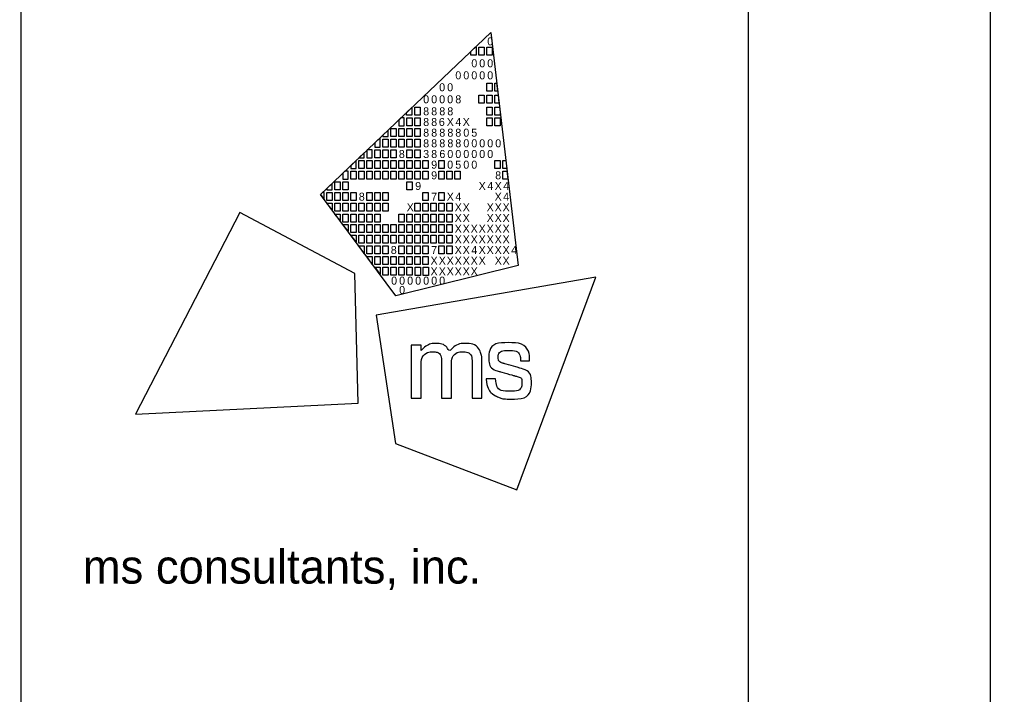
# Model space of a CAD drawing. Extents: x 0 to 34, y 0 to 22.
# Drawn here: x 31.997 to 34, y 2.72 to 4.113 of the extents above; entities that cross this region are included whole.
import ezdxf

# ---------------------------------------------------------------- set-up
doc = ezdxf.new("R2010")
doc.units = 0
for name, color, linetype in [('SH_Border', 7, 'Continuous'), ('SH_Cut_Line', 7, 'Continuous'), ('SH_Data', 7, 'Continuous')]:
    doc.layers.add(name, color=color, linetype=linetype)

msp = doc.modelspace()

# ---------------------------------------------------------------- linework, layer by layer
at = {"layer": 'SH_Border'}
for p, q in [((32, 0.5), (32, 21.5)), ((32.6175, 3.7519), (32.9688, 4.0861)), ((32.9688, 4.0861), (32.9688, 4.0861)), ((32.9688, 4.0861), (33.0253, 3.6052)), ((32.773, 3.543), (32.6175, 3.7519)), ((33.0253, 3.6052), (32.773, 3.543))]:
    msp.add_line(p, q, dxfattribs=at)
for points in [[(1.5, 21.5), (33.5, 21.5), (33.5, 0.5), (1.5, 0.5)], [(32.9279, 4.0472), (32.9369, 4.0558), (32.9389, 4.0558), (32.9389, 4.0393), (32.9279, 4.0393)], [(32.9444, 4.0558), (32.9554, 4.0558), (32.9554, 4.0393), (32.9444, 4.0393)], [(32.9609, 4.0558), (32.9719, 4.0558), (32.9719, 4.0393), (32.9609, 4.0393)], [(32.9606, 3.9815), (32.9716, 3.9815), (32.9716, 3.965), (32.9606, 3.965)], [(32.9771, 3.9815), (32.9811, 3.9815), (32.983, 3.965), (32.9771, 3.965)], [(32.9441, 3.9567), (32.9551, 3.9567), (32.9551, 3.9402), (32.9441, 3.9402)], [(32.9606, 3.9567), (32.9716, 3.9567), (32.9716, 3.9402), (32.9606, 3.9402)], [(32.9771, 3.9567), (32.984, 3.9567), (32.9859, 3.9402), (32.9771, 3.9402)], [(32.7953, 3.9211), (32.8064, 3.9316), (32.8064, 3.9154), (32.7953, 3.9154)], [(32.8123, 3.9319), (32.8233, 3.9319), (32.8233, 3.9154), (32.8123, 3.9154)], [(32.9606, 3.9319), (32.9716, 3.9319), (32.9716, 3.9154), (32.9606, 3.9154)], [(32.9771, 3.9319), (32.9869, 3.9319), (32.9881, 3.9218), (32.9881, 3.9154), (32.9771, 3.9154)], [(32.7958, 3.9099), (32.8068, 3.9099), (32.8068, 3.8934), (32.7958, 3.8934)], [(32.8123, 3.9099), (32.8233, 3.9099), (32.8233, 3.8934), (32.8123, 3.8934)], [(32.9606, 3.9099), (32.9716, 3.9099), (32.9716, 3.8934), (32.9606, 3.8934)], [(32.9771, 3.9099), (32.9881, 3.9099), (32.9881, 3.8934), (32.9771, 3.8934)], [(32.7627, 3.8879), (32.7737, 3.8879), (32.7737, 3.8714), (32.7627, 3.8714)], [(32.7793, 3.8879), (32.7903, 3.8879), (32.7903, 3.8714), (32.7793, 3.8714)], [(32.7958, 3.8879), (32.8068, 3.8879), (32.8068, 3.8714), (32.7958, 3.8714)], [(32.8123, 3.8879), (32.8233, 3.8879), (32.8233, 3.8714), (32.8123, 3.8714)], [(32.7462, 3.8659), (32.7572, 3.8659), (32.7572, 3.8494), (32.7462, 3.8494)], [(32.7627, 3.8659), (32.7737, 3.8659), (32.7737, 3.8494), (32.7627, 3.8494)], [(32.7793, 3.8659), (32.7903, 3.8659), (32.7903, 3.8494), (32.7793, 3.8494)], [(32.7958, 3.8659), (32.8068, 3.8659), (32.8068, 3.8494), (32.7958, 3.8494)], [(32.8123, 3.8659), (32.8233, 3.8659), (32.8233, 3.8494), (32.8123, 3.8494)], [(32.7297, 3.8439), (32.7407, 3.8439), (32.7407, 3.8273), (32.7297, 3.8273)], [(32.7462, 3.8439), (32.7572, 3.8439), (32.7572, 3.8273), (32.7462, 3.8273)], [(32.7627, 3.8439), (32.7737, 3.8439), (32.7737, 3.8273), (32.7627, 3.8273)], [(32.7958, 3.8439), (32.8068, 3.8439), (32.8068, 3.8273), (32.7958, 3.8273)], [(32.8123, 3.8439), (32.8233, 3.8439), (32.8233, 3.8273), (32.8123, 3.8273)], [(32.6967, 3.8218), (32.7077, 3.8218), (32.7077, 3.8053), (32.6967, 3.8053)], [(32.7132, 3.8218), (32.7242, 3.8218), (32.7242, 3.8053), (32.7132, 3.8053)], [(32.7297, 3.8218), (32.7407, 3.8218), (32.7407, 3.8053), (32.7297, 3.8053)], [(32.7462, 3.8218), (32.7572, 3.8218), (32.7572, 3.8053), (32.7462, 3.8053)], [(32.7627, 3.8218), (32.7737, 3.8218), (32.7737, 3.8053), (32.7627, 3.8053)], [(32.7793, 3.8218), (32.7903, 3.8218), (32.7903, 3.8053), (32.7793, 3.8053)], [(32.7958, 3.8218), (32.8068, 3.8218), (32.8068, 3.8053), (32.7958, 3.8053)], [(32.8123, 3.8218), (32.8233, 3.8218), (32.8233, 3.8053), (32.8123, 3.8053)], [(32.8288, 3.8218), (32.8398, 3.8218), (32.8398, 3.8053), (32.8288, 3.8053)], [(32.8618, 3.8218), (32.8728, 3.8218), (32.8728, 3.8053), (32.8618, 3.8053)], [(32.9771, 3.8218), (32.9881, 3.8218), (32.9881, 3.8053), (32.9771, 3.8053)], [(32.9935, 3.8218), (32.9998, 3.8218), (33.0018, 3.8053), (32.9935, 3.8053)], [(32.6802, 3.7998), (32.6912, 3.7998), (32.6912, 3.7833), (32.6802, 3.7833)], [(32.6967, 3.7998), (32.7077, 3.7998), (32.7077, 3.7833), (32.6967, 3.7833)], [(32.7132, 3.7998), (32.7242, 3.7998), (32.7242, 3.7833), (32.7132, 3.7833)], [(32.7297, 3.7998), (32.7407, 3.7998), (32.7407, 3.7833), (32.7297, 3.7833)], [(32.7462, 3.7998), (32.7572, 3.7998), (32.7572, 3.7833), (32.7462, 3.7833)], [(32.7627, 3.7998), (32.7737, 3.7998), (32.7737, 3.7833), (32.7627, 3.7833)], [(32.7793, 3.7998), (32.7903, 3.7998), (32.7903, 3.7833), (32.7793, 3.7833)], [(32.7958, 3.7998), (32.8068, 3.7998), (32.8068, 3.7833), (32.7958, 3.7833)], [(32.8123, 3.7998), (32.8233, 3.7998), (32.8233, 3.7833), (32.8123, 3.7833)], [(32.8288, 3.7998), (32.8398, 3.7998), (32.8398, 3.7833), (32.8288, 3.7833)], [(32.8618, 3.7998), (32.8728, 3.7998), (32.8728, 3.7833), (32.8618, 3.7833)], [(32.8783, 3.7998), (32.8893, 3.7998), (32.8893, 3.7833), (32.8783, 3.7833)], [(32.8947, 3.7998), (32.9057, 3.7998), (32.9057, 3.7833), (32.8947, 3.7833)], [(32.9935, 3.7998), (33.0024, 3.7998), (33.0044, 3.7833), (32.9935, 3.7833)], [(32.6471, 3.7778), (32.6581, 3.7778), (32.6581, 3.7613), (32.6471, 3.7613)], [(32.6637, 3.7778), (32.6747, 3.7778), (32.6747, 3.7613), (32.6637, 3.7613)], [(32.7958, 3.7778), (32.8068, 3.7778), (32.8068, 3.7613), (32.7958, 3.7613)], [(32.6306, 3.7558), (32.6416, 3.7558), (32.6416, 3.7393), (32.6306, 3.7393)], [(32.6471, 3.7558), (32.6581, 3.7558), (32.6581, 3.7393), (32.6471, 3.7393)], [(32.6637, 3.7558), (32.6747, 3.7558), (32.6747, 3.7393), (32.6637, 3.7393)], [(32.6802, 3.7558), (32.6912, 3.7558), (32.6912, 3.7393), (32.6802, 3.7393)], [(32.7132, 3.7558), (32.7242, 3.7558), (32.7242, 3.7393), (32.7132, 3.7393)], [(32.7297, 3.7558), (32.7407, 3.7558), (32.7407, 3.7393), (32.7297, 3.7393)], [(32.7462, 3.7558), (32.7572, 3.7558), (32.7572, 3.7393), (32.7462, 3.7393)], [(32.8288, 3.7558), (32.8398, 3.7558), (32.8398, 3.7393), (32.8288, 3.7393)], [(32.8618, 3.7558), (32.8728, 3.7558), (32.8728, 3.7393), (32.8618, 3.7393)], [(32.6306, 3.7338), (32.6416, 3.7338), (32.6416, 3.72)], [(32.6471, 3.7338), (32.6581, 3.7338), (32.6581, 3.7173), (32.6471, 3.7173)], [(32.6637, 3.7338), (32.6747, 3.7338), (32.6747, 3.7173), (32.6637, 3.7173)], [(32.6802, 3.7338), (32.6912, 3.7338), (32.6912, 3.7173), (32.6802, 3.7173)], [(32.6967, 3.7338), (32.7077, 3.7338), (32.7077, 3.7173), (32.6967, 3.7173)], [(32.7132, 3.7338), (32.7242, 3.7338), (32.7242, 3.7173), (32.7132, 3.7173)], [(32.7297, 3.7338), (32.7407, 3.7338), (32.7407, 3.7173), (32.7297, 3.7173)], [(32.7462, 3.7338), (32.7572, 3.7338), (32.7572, 3.7173), (32.7462, 3.7173)], [(32.8123, 3.7338), (32.8233, 3.7338), (32.8233, 3.7173), (32.8123, 3.7173)], [(32.8288, 3.7338), (32.8398, 3.7338), (32.8398, 3.7173), (32.8288, 3.7173)], [(32.8453, 3.7338), (32.8563, 3.7338), (32.8563, 3.7173), (32.8453, 3.7173)], [(32.8618, 3.7338), (32.8728, 3.7338), (32.8728, 3.7173), (32.8618, 3.7173)], [(32.8783, 3.7338), (32.8893, 3.7338), (32.8893, 3.7173), (32.8783, 3.7173)], [(32.6471, 3.7117), (32.6581, 3.7117), (32.6581, 3.698)], [(32.6637, 3.7117), (32.6747, 3.7117), (32.6747, 3.6952), (32.6637, 3.6952)], [(32.6802, 3.7117), (32.6912, 3.7117), (32.6912, 3.6952), (32.6802, 3.6952)], [(32.6967, 3.7117), (32.7077, 3.7117), (32.7077, 3.6952), (32.6967, 3.6952)], [(32.7132, 3.7117), (32.7242, 3.7117), (32.7242, 3.6952), (32.7132, 3.6952)], [(32.7297, 3.7117), (32.7407, 3.7117), (32.7407, 3.6952), (32.7297, 3.6952)], [(32.7793, 3.7117), (32.7903, 3.7117), (32.7903, 3.6952), (32.7793, 3.6952)], [(32.7958, 3.7117), (32.8068, 3.7117), (32.8068, 3.6952), (32.7958, 3.6952)], [(32.8123, 3.7117), (32.8233, 3.7117), (32.8233, 3.6952), (32.8123, 3.6952)], [(32.8288, 3.7117), (32.8398, 3.7117), (32.8398, 3.6952), (32.8288, 3.6952)], [(32.8453, 3.7117), (32.8563, 3.7117), (32.8563, 3.6952), (32.8453, 3.6952)], [(32.8618, 3.7117), (32.8728, 3.7117), (32.8728, 3.6952), (32.8618, 3.6952)], [(32.8783, 3.7117), (32.8893, 3.7117), (32.8893, 3.6952), (32.8783, 3.6952)], [(32.6637, 3.6897), (32.6747, 3.6897), (32.6747, 3.676)], [(32.6747, 3.6897), (32.6747, 3.6897), (32.6747, 3.6897)], [(32.6802, 3.6897), (32.6912, 3.6897), (32.6912, 3.6732), (32.6802, 3.6732)], [(32.6967, 3.6897), (32.7077, 3.6897), (32.7077, 3.6732), (32.6967, 3.6732)], [(32.7132, 3.6897), (32.7242, 3.6897), (32.7242, 3.6732), (32.7132, 3.6732)], [(32.7297, 3.6897), (32.7407, 3.6897), (32.7407, 3.6732), (32.7297, 3.6732)], [(32.7462, 3.6897), (32.7572, 3.6897), (32.7572, 3.6732), (32.7462, 3.6732)], [(32.7627, 3.6897), (32.7737, 3.6897), (32.7737, 3.6732), (32.7627, 3.6732)], [(32.7793, 3.6897), (32.7903, 3.6897), (32.7903, 3.6732), (32.7793, 3.6732)], [(32.7958, 3.6897), (32.8068, 3.6897), (32.8068, 3.6732), (32.7958, 3.6732)], [(32.8123, 3.6897), (32.8233, 3.6897), (32.8233, 3.6732), (32.8123, 3.6732)], [(32.8288, 3.6897), (32.8398, 3.6897), (32.8398, 3.6732), (32.8288, 3.6732)], [(32.8453, 3.6897), (32.8563, 3.6897), (32.8563, 3.6732), (32.8453, 3.6732)], [(32.8618, 3.6897), (32.8728, 3.6897), (32.8728, 3.6732), (32.8618, 3.6732)], [(32.8783, 3.6897), (32.8893, 3.6897), (32.8893, 3.6732), (32.8783, 3.6732)], [(32.6802, 3.6677), (32.6912, 3.6677), (32.6912, 3.654)], [(32.6967, 3.6677), (32.7077, 3.6677), (32.7077, 3.6512), (32.6967, 3.6512)], [(32.7132, 3.6677), (32.7242, 3.6677), (32.7242, 3.6512), (32.7132, 3.6512)], [(32.7297, 3.6677), (32.7407, 3.6677), (32.7407, 3.6512), (32.7297, 3.6512)], [(32.7462, 3.6677), (32.7572, 3.6677), (32.7572, 3.6512), (32.7462, 3.6512)], [(32.7627, 3.6677), (32.7737, 3.6677), (32.7737, 3.6512), (32.7627, 3.6512)], [(32.7793, 3.6677), (32.7903, 3.6677), (32.7903, 3.6512), (32.7793, 3.6512)], [(32.7958, 3.6677), (32.8068, 3.6677), (32.8068, 3.6512), (32.7958, 3.6512)], [(32.8123, 3.6677), (32.8233, 3.6677), (32.8233, 3.6512), (32.8123, 3.6512)], [(32.8288, 3.6677), (32.8398, 3.6677), (32.8398, 3.6512), (32.8288, 3.6512)], [(32.8453, 3.6677), (32.8563, 3.6677), (32.8563, 3.6512), (32.8453, 3.6512)], [(32.8618, 3.6677), (32.8728, 3.6677), (32.8728, 3.6512), (32.8618, 3.6512)], [(32.8783, 3.6677), (32.8893, 3.6677), (32.8893, 3.6512), (32.8783, 3.6512)], [(32.7077, 3.6305), (32.6965, 3.6457), (32.7077, 3.6457)], [(32.7132, 3.6457), (32.7242, 3.6457), (32.7242, 3.6292), (32.7132, 3.6292)], [(32.7297, 3.6457), (32.7407, 3.6457), (32.7407, 3.6292), (32.7297, 3.6292)], [(32.7462, 3.6457), (32.7572, 3.6457), (32.7572, 3.6292), (32.7462, 3.6292)], [(32.7793, 3.6457), (32.7903, 3.6457), (32.7903, 3.6292), (32.7793, 3.6292)], [(32.7958, 3.6457), (32.8068, 3.6457), (32.8068, 3.6292), (32.7958, 3.6292)], [(32.8123, 3.6457), (32.8233, 3.6457), (32.8233, 3.6292), (32.8123, 3.6292)], [(32.8288, 3.6457), (32.8398, 3.6457), (32.8398, 3.6292), (32.8288, 3.6292)], [(32.8618, 3.6457), (32.8728, 3.6457), (32.8728, 3.6292), (32.8618, 3.6292)], [(32.8783, 3.6457), (32.8893, 3.6457), (32.8893, 3.6292), (32.8783, 3.6292)], [(32.724, 3.6082), (32.7132, 3.6237), (32.7242, 3.6237)], [(32.7297, 3.6237), (32.7407, 3.6237), (32.7407, 3.6072), (32.7297, 3.6072)], [(32.7462, 3.6237), (32.7572, 3.6237), (32.7572, 3.6072), (32.7462, 3.6072)], [(32.7627, 3.6237), (32.7737, 3.6237), (32.7737, 3.6072), (32.7627, 3.6072)], [(32.7793, 3.6237), (32.7903, 3.6237), (32.7903, 3.6072), (32.7793, 3.6072)], [(32.7958, 3.6237), (32.8068, 3.6237), (32.8068, 3.6072), (32.7958, 3.6072)], [(32.8123, 3.6237), (32.8233, 3.6237), (32.8233, 3.6072), (32.8123, 3.6072)], [(32.8288, 3.6237), (32.8398, 3.6237), (32.8398, 3.6072), (32.8288, 3.6072)], [(32.7302, 3.6017), (32.7407, 3.6017), (32.7408, 3.5875)], [(32.7463, 3.6017), (32.7573, 3.6017), (32.7573, 3.5852), (32.7463, 3.5852)], [(32.763, 3.6017), (32.774, 3.6017), (32.774, 3.5852), (32.763, 3.5852)], [(32.7794, 3.6017), (32.7904, 3.6017), (32.7904, 3.5852), (32.7794, 3.5852)], [(32.796, 3.6017), (32.807, 3.6017), (32.807, 3.5852), (32.796, 3.5852)], [(32.8129, 3.6017), (32.8239, 3.6017), (32.8239, 3.5851), (32.8129, 3.5851)], [(32.8296, 3.6017), (32.8406, 3.6017), (32.8406, 3.5851), (32.8296, 3.5851)]]:
    msp.add_lwpolyline(points, close=True, dxfattribs=at)
for points in [[(32.7903, 3.9099), (32.7836, 3.9099), (32.7793, 3.9058), (32.7793, 3.8934), (32.7903, 3.8934), (32.7903, 3.9099)], [(32.7407, 3.8691), (32.7297, 3.8587), (32.7297, 3.8494), (32.7407, 3.8494), (32.7407, 3.8691)], [(32.7572, 3.8849), (32.7462, 3.8744), (32.7462, 3.8714), (32.7572, 3.8714), (32.7572, 3.8849)], [(32.7077, 3.8377), (32.6968, 3.8273), (32.7077, 3.8273), (32.7077, 3.8377)], [(32.7242, 3.8439), (32.7141, 3.8439), (32.7132, 3.843), (32.7132, 3.8273), (32.7242, 3.8273), (32.7242, 3.8439)], [(32.6912, 3.822), (32.6802, 3.8115), (32.6802, 3.8053), (32.6912, 3.8053), (32.6912, 3.822)], [(32.6747, 3.7998), (32.6679, 3.7998), (32.6637, 3.7958), (32.6637, 3.7833), (32.6747, 3.7833), (32.6747, 3.7998)], [(32.6416, 3.7749), (32.6306, 3.7644), (32.6306, 3.7613), (32.6416, 3.7613), (32.6416, 3.7749)], [(32.6251, 3.7558), (32.6216, 3.7558), (32.6175, 3.7519), (32.6251, 3.7417), (32.6251, 3.7558)], [(32.4512, 3.7149), (32.2359, 3.2988), (32.6956, 3.3215), (32.6884, 3.5892), (32.4512, 3.7149)], [(33.0229, 3.1422), (33.1859, 3.5814), (32.7324, 3.5029), (32.7722, 3.2381), (33.0229, 3.1422)]]:
    msp.add_lwpolyline(points, dxfattribs=at)
for points in [[(32.9595, 3.3709), (32.9595, 3.3709), (32.9595, 3.3717), (32.9595, 3.3717), (32.9595, 3.3717), (32.9603, 3.3717), (32.9603, 3.3717), (32.9603, 3.3717), (32.9783, 3.3717), (32.9783, 3.3717), (32.9783, 3.3717), (32.9789, 3.3717), (32.9789, 3.3717), (32.9789, 3.3717), (32.979, 3.371), (32.979, 3.371), (32.9803, 3.3554), (32.9887, 3.346), (33.009, 3.346), (33.0273, 3.346), (33.0333, 3.3554), (33.0333, 3.3631), (33.0333, 3.3732), (33.0256, 3.3758), (33.0175, 3.378), (33.0175, 3.378), (32.987, 3.3867), (32.987, 3.3867), (32.972, 3.3909), (32.9648, 3.4019), (32.9648, 3.4142), (32.9648, 3.4303), (32.9768, 3.4462), (33.0052, 3.4462), (33.0348, 3.4462), (33.0489, 3.4285), (33.0489, 3.4095), (33.0489, 3.4095), (33.0489, 3.4087), (33.0489, 3.4087), (33.0489, 3.4087), (33.0482, 3.4087), (33.0482, 3.4087), (33.0482, 3.4087), (33.0312, 3.4087), (33.0312, 3.4087), (33.0312, 3.4087), (33.0305, 3.4087), (33.0305, 3.4087), (33.0305, 3.4087), (33.0305, 3.4094), (33.0305, 3.4094), (33.0301, 3.4208), (33.0226, 3.43), (33.0056, 3.43), (32.9891, 3.43), (32.9843, 3.4218), (32.9843, 3.4157), (32.9843, 3.4108), (32.9869, 3.4059), (32.9959, 3.4033), (32.9959, 3.4033), (33.0255, 3.3948), (33.0255, 3.3948), (33.0462, 3.3889), (33.0527, 3.3777), (33.0527, 3.3639), (33.0527, 3.3462), (33.041, 3.3298), (33.0087, 3.3298), (32.9952, 3.3298), (32.9877, 3.3321), (32.9823, 3.3348), (32.969, 3.3414), (32.9609, 3.3536), (32.9595, 3.3709)], [(32.8048, 3.3315), (32.8048, 3.3315), (32.8048, 3.4409), (32.8048, 3.4409), (32.8048, 3.4409), (32.8255, 3.4409), (32.8255, 3.4409), (32.8255, 3.4409), (32.8255, 3.4297), (32.8255, 3.4297), (32.8346, 3.4399), (32.8457, 3.4445), (32.8555, 3.4445), (32.8688, 3.4445), (32.8791, 3.4372), (32.8837, 3.4266), (32.8915, 3.4381), (32.905, 3.4446), (32.9166, 3.4446), (32.9325, 3.4446), (32.9451, 3.435), (32.9494, 3.4213), (32.9494, 3.4212), (32.9494, 3.4212), (32.9494, 3.4212), (32.9501, 3.419), (32.9506, 3.4172), (32.9506, 3.4071), (32.9506, 3.4071), (32.9506, 3.3314), (32.9506, 3.3314), (32.9506, 3.3314), (32.9303, 3.3314), (32.9303, 3.3314), (32.9303, 3.3314), (32.9303, 3.4048), (32.9303, 3.4048), (32.9303, 3.4201), (32.9219, 3.4274), (32.911, 3.4274), (32.8995, 3.4274), (32.8879, 3.4171), (32.8879, 3.4001), (32.8879, 3.4001), (32.8879, 3.3315), (32.8879, 3.3315), (32.8879, 3.3315), (32.8674, 3.3315), (32.8674, 3.3315), (32.8674, 3.3315), (32.8674, 3.4059), (32.8674, 3.4059), (32.8674, 3.4203), (32.8588, 3.4274), (32.8496, 3.4274), (32.8384, 3.4274), (32.8254, 3.417), (32.8254, 3.3962), (32.8254, 3.3962), (32.8254, 3.3315), (32.8254, 3.3315), (32.8254, 3.3315), (32.8048, 3.3315), (32.8048, 3.3315)]]:
    msp.add_open_spline(points, degree=3, dxfattribs=at)
at = {"layer": 'SH_Cut_Line'}
msp.add_lwpolyline([(0, 0), (34, 0), (34, 22), (0, 22)], close=True, dxfattribs=at)
at = {"layer": 'SH_Data'}
msp.add_line((32.75, 3.5), (32.75, 3.5), dxfattribs=at)

# ---------------------------------------------------------------- texts
at = {"layer": 'SH_Border'}
for s, height, p in [('0', 0.0165, (32.9617, 4.0597)), ('0', 0.0165, (32.9288, 4.0145)), ('0', 0.0165, (32.9452, 4.0145)), ('0', 0.0165, (32.9617, 4.0145)), ('0', 0.0165, (32.8958, 3.9897)), ('0', 0.0165, (32.9123, 3.9897)), ('0', 0.0165, (32.9288, 3.9897)), ('0', 0.0165, (32.9452, 3.9897)), ('0', 0.0165, (32.9617, 3.9897)), ('0', 0.0165, (32.8625, 3.965)), ('0', 0.0165, (32.879, 3.965)), ('0', 0.0165, (32.8295, 3.9402)), ('0', 0.0165, (32.846, 3.9402)), ('0', 0.0165, (32.8625, 3.9402)), ('0', 0.0165, (32.879, 3.9402)), ('8', 0.0165, (32.8958, 3.9402)), ('8', 0.0165, (32.8295, 3.9154)), ('8', 0.0165, (32.846, 3.9154)), ('8', 0.0165, (32.8628, 3.9154)), ('8', 0.0165, (32.8793, 3.9154)), ('8', 0.0165, (32.8295, 3.8934)), ('8', 0.0165, (32.846, 3.8934)), ('6', 0.0165, (32.8618, 3.8934)), ('X', 0.0165, (32.8781, 3.8934)), ('4', 0.0165, (32.8958, 3.8934)), ('X', 0.0165, (32.911, 3.8934)), ('8', 0.0165, (32.8295, 3.8713)), ('8', 0.0165, (32.846, 3.8713)), ('8', 0.0165, (32.8628, 3.8713)), ('8', 0.0165, (32.8794, 3.8713)), ('8', 0.0165, (32.8958, 3.8713)), ('0', 0.0165, (32.9123, 3.8713)), ('5', 0.0165, (32.9287, 3.8713)), ('8', 0.0165, (32.8295, 3.8494)), ('8', 0.0165, (32.846, 3.8494)), ('8', 0.0165, (32.8628, 3.8494)), ('8', 0.0165, (32.8794, 3.8494)), ('8', 0.0165, (32.8958, 3.8494)), ('0', 0.0165, (32.9123, 3.8494)), ('0', 0.0165, (32.9288, 3.8494)), ('0', 0.0165, (32.9452, 3.8494)), ('0', 0.0165, (32.9617, 3.8494)), ('0', 0.0165, (32.9782, 3.8494)), ('8', 0.0165, (32.7793, 3.8273)), ('3', 0.0165, (32.8295, 3.8273)), ('8', 0.0165, (32.846, 3.8273)), ('6', 0.0165, (32.8629, 3.8273)), ('0', 0.0165, (32.8793, 3.8273)), ('0', 0.0165, (32.8958, 3.8273)), ('0', 0.0165, (32.9123, 3.8273)), ('0', 0.0165, (32.9288, 3.8273)), ('0', 0.0165, (32.9452, 3.8273)), ('0', 0.0165, (32.9617, 3.8273)), ('9', 0.0165, (32.846, 3.8053)), ('0', 0.0165, (32.879, 3.8053)), ('5', 0.0165, (32.8957, 3.8053)), ('0', 0.0165, (32.9123, 3.8053)), ('0', 0.0165, (32.9288, 3.8053)), ('9', 0.0165, (32.846, 3.7833)), ('8', 0.0165, (32.9781, 3.7833)), ('9', 0.0165, (32.813, 3.7613)), ('X', 0.0165, (32.9439, 3.7613)), ('4', 0.0165, (32.9617, 3.7613)), ('X', 0.0165, (32.9769, 3.7613)), ('4', 0.0165, (32.9946, 3.7613)), ('8', 0.0165, (32.6967, 3.7393)), ('7', 0.0165, (32.846, 3.7393)), ('X', 0.0165, (32.8781, 3.7393)), ('4', 0.0165, (32.8958, 3.7393)), ('X', 0.0165, (32.9769, 3.7393)), ('4', 0.0165, (32.9946, 3.7393)), ('X', 0.0165, (32.7955, 3.7173)), ('X', 0.0165, (32.8945, 3.7173)), ('X', 0.0165, (32.911, 3.7173)), ('X', 0.0165, (32.9604, 3.7173)), ('X', 0.0165, (32.9769, 3.7173)), ('X', 0.0165, (32.9933, 3.7173)), ('X', 0.0165, (32.8945, 3.6952)), ('X', 0.0165, (32.911, 3.6952)), ('X', 0.0165, (32.9604, 3.6952)), ('X', 0.0165, (32.9769, 3.6952)), ('X', 0.0165, (32.9933, 3.6952)), ('X', 0.0165, (32.8945, 3.6732)), ('X', 0.0165, (32.911, 3.6732)), ('X', 0.0165, (32.9274, 3.6732)), ('X', 0.0165, (32.9439, 3.6732)), ('X', 0.0165, (32.9604, 3.6732)), ('X', 0.0165, (32.9769, 3.6732)), ('X', 0.0165, (32.9933, 3.6732)), ('X', 0.0165, (32.8945, 3.6512)), ('X', 0.0165, (32.911, 3.6512)), ('X', 0.0165, (32.9274, 3.6512)), ('X', 0.0165, (32.9439, 3.6512)), ('X', 0.0165, (32.9604, 3.6512)), ('X', 0.0165, (32.9769, 3.6512)), ('X', 0.0165, (32.9933, 3.6512)), ('8', 0.0165, (32.7627, 3.6292)), ('7', 0.0165, (32.846, 3.6292)), ('X', 0.0165, (32.8945, 3.6292)), ('X', 0.0165, (32.911, 3.6292)), ('4', 0.0165, (32.9288, 3.6292)), ('X', 0.0165, (32.9439, 3.6292)), ('X', 0.0165, (32.9604, 3.6292)), ('X', 0.0165, (32.9769, 3.6292)), ('X', 0.0165, (32.9933, 3.6292)), ('4', 0.0165, (33.0111, 3.6292)), ('X', 0.0165, (32.8447, 3.6072)), ('X', 0.0165, (32.8616, 3.6072)), ('X', 0.0165, (32.878, 3.6072)), ('X', 0.0165, (32.8945, 3.6072)), ('X', 0.0165, (32.911, 3.6072)), ('X', 0.0165, (32.9274, 3.6072)), ('X', 0.0165, (32.9439, 3.6072)), ('X', 0.0165, (32.9771, 3.6072)), ('X', 0.0165, (32.9933, 3.6072)), ('X', 0.0165, (32.8447, 3.5851)), ('X', 0.0165, (32.8616, 3.5851)), ('X', 0.0165, (32.878, 3.5851)), ('X', 0.0165, (32.8945, 3.5851)), ('X', 0.0165, (32.911, 3.5851)), ('X', 0.0165, (32.9274, 3.5851)), ('0', 0.0165, (32.7634, 3.5659)), ('0', 0.0165, (32.7799, 3.5659)), ('0', 0.0165, (32.7965, 3.5659)), ('0', 0.0165, (32.813, 3.5659)), ('0', 0.0165, (32.8295, 3.5659)), ('0', 0.0165, (32.846, 3.5659)), ('0', 0.0165, (32.8625, 3.5659)), ('0', 0.0165, (32.7799, 3.5467)), ('ms consultants, inc.', 0.07, (32.1273, 2.9489))]:
    msp.add_text(s, height=height, rotation=360, dxfattribs=at).set_placement(p)

doc.saveas('drawing.dxf')
